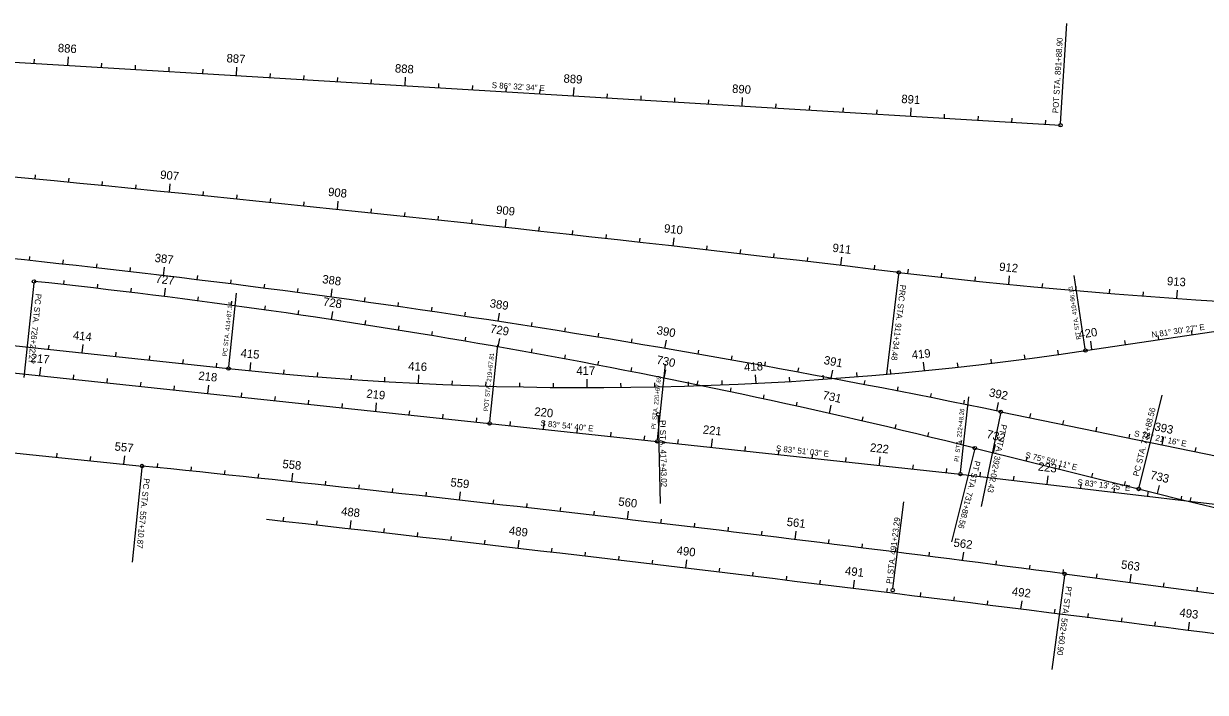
# Model space of a CAD drawing. Extents: x 919452 to 931278, y 583254 to 665650.
# Drawn here: x 927014 to 927714, y 636499 to 636895 of the extents above; entities that cross this region are included whole.
import ezdxf

# ---------------------------------------------------------------- set-up
doc = ezdxf.new("R2010")
doc.units = 0
for name, color, linetype in [('LaneLine', 7, 'Continuous'), ('PMStripe24W', 7, 'Continuous'), ('Scratch1_dp', 7, 'Continuous'), ('ScratchEle_dp', 7, 'Continuous'), ('ShldrHatch', 7, 'Continuous'), ('TollReader', 7, 'Continuous')]:
    doc.layers.add(name, color=color, linetype=linetype)

msp = doc.modelspace()

# ---------------------------------------------------------------- linework, layer by layer
at = {"layer": 'LaneLine'}
for p, q in [((927628.15, 636835.87), (927631.73, 636895.12)), ((927532.16, 636746.7), (927525.07, 636687.36)), ((927642.72, 636702.37), (927636.23, 636745.83)), ((927020.08, 636741.37), (927014.11, 636685.5)), ((927135.47, 636691.73), (927140.13, 636735.38)), ((927290.06, 636659.14), (927294.92, 636704.74)), ((927389.37, 636648.55), (927394.15, 636693.33)), ((927674.6, 636620.31), (927688.23, 636674.91)), ((927568.9, 636629.21), (927573.72, 636673.98)), ((927389.82, 636662.59), (927390.9, 636610.77)), ((927592.52, 636664.14), (927581.17, 636609.04)), ((927577.09, 636642.59), (927563.49, 636588.08)), ((927084.11, 636631.97), (927078.38, 636576.07)), ((927528.88, 636560.37), (927535.2, 636611.74)), ((927630.37, 636568.06), (927623.04, 636512.38))]:
    msp.add_line(p, q, dxfattribs=at)
for centre in [(927628.09, 636834.88), (927532.27, 636747.7), (927020.19, 636742.37), (927642.87, 636701.38), (927135.36, 636690.73), (927389.8, 636663.59), (927592.72, 636665.12), (927289.95, 636658.15), (927389.26, 636647.56), (927577.33, 636643.56), (927084.21, 636632.96), (927568.79, 636628.21), (927674.36, 636619.34), (927630.5, 636569.05), (927528.76, 636559.38)]:
    msp.add_circle(centre, 1, dxfattribs=at)
at = {"layer": 'Scratch1_dp'}
for p, q in [((927020.31, 636871.59), (927020.46, 636874.09)), ((927060.23, 636869.18), (927060.38, 636871.68)), ((927080.2, 636867.98), (927080.35, 636870.47)), ((927100.16, 636866.77), (927100.31, 636869.27)), ((927120.12, 636865.56), (927120.27, 636868.06)), ((927160.05, 636863.15), (927160.2, 636865.65)), ((927180.01, 636861.95), (927180.17, 636864.44)), ((927199.98, 636860.74), (927200.13, 636863.24)), ((927219.94, 636859.53), (927220.09, 636862.03)), ((927259.87, 636857.12), (927260.02, 636859.62)), ((927279.83, 636855.92), (927279.98, 636858.41)), ((927299.8, 636854.71), (927299.95, 636857.2)), ((927319.76, 636853.5), (927319.91, 636856)), ((927359.69, 636851.09), (927359.84, 636853.59)), ((927379.65, 636849.89), (927379.8, 636852.38)), ((927399.61, 636848.68), (927399.76, 636851.17)), ((927419.58, 636847.47), (927419.73, 636849.97)), ((927459.5, 636845.06), (927459.66, 636847.56)), ((927479.47, 636843.85), (927479.62, 636846.35)), ((927499.43, 636842.65), (927499.58, 636845.14)), ((927519.4, 636841.44), (927519.55, 636843.94)), ((927559.32, 636839.03), (927559.47, 636841.53)), ((927579.29, 636837.82), (927579.44, 636840.32)), ((927599.25, 636836.62), (927599.4, 636839.11)), ((927619.21, 636835.41), (927619.36, 636837.91)), ((927020.78, 636802.98), (927021.02, 636805.47)), ((927040.69, 636801.04), (927040.93, 636803.53)), ((927060.59, 636799.09), (927060.84, 636801.58)), ((927080.5, 636797.12), (927080.74, 636799.61)), ((927120.3, 636793.13), (927120.55, 636795.62)), ((927140.2, 636791.11), (927140.45, 636793.6)), ((927160.09, 636789.07), (927160.35, 636791.56)), ((927179.99, 636787.01), (927180.24, 636789.5)), ((927219.77, 636782.85), (927220.03, 636785.34)), ((927239.66, 636780.74), (927239.92, 636783.23)), ((927259.54, 636778.62), (927259.81, 636781.1)), ((927279.43, 636776.47), (927279.7, 636778.96)), ((927319.19, 636772.14), (927319.47, 636774.62)), ((927339.07, 636769.94), (927339.35, 636772.43)), ((927358.95, 636767.73), (927359.23, 636770.21)), ((927378.82, 636765.5), (927379.1, 636767.98)), ((927418.57, 636760.99), (927418.85, 636763.47)), ((927438.44, 636758.71), (927438.72, 636761.19)), ((927458.31, 636756.41), (927458.59, 636758.89)), ((927017.46, 636754.73), (927017.73, 636757.21)), ((927037.35, 636752.58), (927037.62, 636755.07)), ((927057.22, 636750.37), (927057.5, 636752.85)), ((927478.17, 636754.09), (927478.46, 636756.58)), ((927517.9, 636749.41), (927518.19, 636751.89)), ((927077.09, 636748.09), (927077.38, 636750.58)), ((927116.81, 636743.34), (927117.12, 636745.82)), ((927537.76, 636747.05), (927538.05, 636749.53)), ((927557.63, 636744.77), (927557.9, 636747.25)), ((927577.51, 636742.61), (927577.77, 636745.1)), ((927037.82, 636740.45), (927038.09, 636742.93)), ((927057.69, 636738.19), (927057.98, 636740.67)), ((927077.55, 636735.83), (927077.85, 636738.31)), ((927136.66, 636740.86), (927136.97, 636743.34)), ((927156.49, 636738.32), (927156.82, 636740.79)), ((927176.32, 636735.7), (927176.65, 636738.18)), ((927617.31, 636738.67), (927617.55, 636741.16)), ((927637.23, 636736.88), (927637.45, 636739.37)), ((927657.16, 636735.21), (927657.37, 636737.7)), ((927117.23, 636730.83), (927117.56, 636733.31)), ((927137.06, 636728.18), (927137.4, 636730.66)), ((927215.95, 636730.28), (927216.3, 636732.76)), ((927677.1, 636733.66), (927677.29, 636736.16)), ((927156.87, 636725.44), (927157.22, 636727.91)), ((927176.67, 636722.6), (927177.03, 636725.07)), ((927235.76, 636727.48), (927236.11, 636729.95)), ((927255.55, 636724.6), (927255.91, 636727.07)), ((927275.33, 636721.66), (927275.7, 636724.13)), ((927216.22, 636716.63), (927216.6, 636719.1)), ((927314.86, 636715.58), (927315.25, 636718.05)), ((927235.97, 636713.5), (927236.37, 636715.96)), ((927255.71, 636710.27), (927256.12, 636712.74)), ((927275.43, 636706.95), (927275.85, 636709.41)), ((927334.62, 636712.44), (927335.01, 636714.9)), ((927354.36, 636709.23), (927354.76, 636711.7)), ((927686.26, 636707.86), (927685.89, 636710.33)), ((927706.04, 636710.81), (927705.67, 636713.28)), ((927028.83, 636702.1), (927029.09, 636704.58)), ((927314.83, 636700.01), (927315.27, 636702.47)), ((927374.09, 636705.96), (927374.5, 636708.42)), ((927666.48, 636704.9), (927666.11, 636707.38)), ((927068.6, 636697.85), (927068.87, 636700.34)), ((927088.49, 636695.73), (927088.75, 636698.22)), ((927108.37, 636693.61), (927108.64, 636696.1)), ((927334.5, 636696.4), (927334.96, 636698.86)), ((927354.15, 636692.7), (927354.62, 636695.15)), ((927413.52, 636699.21), (927413.95, 636701.68)), ((927433.21, 636695.74), (927433.65, 636698.21)), ((927587.24, 636693.87), (927586.94, 636696.35)), ((927607.09, 636696.37), (927606.76, 636698.84)), ((927626.9, 636699.06), (927626.56, 636701.54)), ((927128.26, 636691.49), (927128.53, 636693.98)), ((927168.06, 636687.52), (927168.29, 636690)), ((927187.99, 636685.82), (927188.19, 636688.31)), ((927373.79, 636688.9), (927374.27, 636691.35)), ((927452.9, 636692.21), (927453.34, 636694.67)), ((927472.57, 636688.61), (927473.02, 636691.06)), ((927507.65, 636685.87), (927507.45, 636688.36)), ((927527.58, 636687.57), (927527.35, 636690.06)), ((927567.38, 636691.57), (927567.1, 636694.06)), ((927043.54, 636684.44), (927043.8, 636686.92)), ((927063.42, 636682.32), (927063.69, 636684.8)), ((927083.31, 636680.19), (927083.58, 636682.68)), ((927207.94, 636684.32), (927208.11, 636686.82)), ((927227.89, 636683.03), (927228.04, 636685.52)), ((927267.84, 636681.04), (927267.94, 636683.53)), ((927287.83, 636680.34), (927287.91, 636682.84)), ((927307.82, 636679.84), (927307.87, 636682.34)), ((927327.82, 636679.55), (927327.85, 636682.05)), ((927367.82, 636679.55), (927367.8, 636682.05)), ((927387.82, 636679.86), (927387.77, 636682.35)), ((927407.81, 636680.36), (927407.74, 636682.86)), ((927413, 636681), (927413.51, 636683.45)), ((927427.8, 636681.06), (927427.7, 636683.56)), ((927467.75, 636683.07), (927467.6, 636685.56)), ((927487.71, 636684.37), (927487.53, 636686.86)), ((927511.88, 636681.2), (927512.35, 636683.66)), ((927103.2, 636678.07), (927103.46, 636680.56)), ((927142.97, 636673.83), (927143.24, 636676.32)), ((927162.86, 636671.71), (927163.12, 636674.19)), ((927432.58, 636676.91), (927433.09, 636679.36)), ((927452.14, 636672.73), (927452.66, 636675.17)), ((927531.52, 636677.4), (927531.99, 636679.86)), ((927551.14, 636673.54), (927551.63, 636675.99)), ((927182.75, 636669.59), (927183.01, 636672.07)), ((927202.63, 636667.47), (927202.9, 636669.95)), ((927471.67, 636668.45), (927472.21, 636670.89)), ((927570.75, 636669.61), (927571.24, 636672.06)), ((927242.41, 636663.22), (927242.67, 636665.71)), ((927262.3, 636661.1), (927262.56, 636663.59)), ((927282.18, 636658.98), (927282.45, 636661.47)), ((927510.68, 636659.6), (927511.25, 636662.04)), ((927609.93, 636661.58), (927610.44, 636664.02)), ((927302.07, 636656.86), (927302.33, 636659.34)), ((927341.84, 636652.61), (927342.11, 636655.1)), ((927530.15, 636655.04), (927530.73, 636657.47)), ((927629.52, 636657.54), (927630.03, 636659.99)), ((927649.11, 636653.5), (927649.61, 636655.95)), ((927361.73, 636650.49), (927362, 636652.98)), ((927381.62, 636648.37), (927381.88, 636650.86)), ((927401.5, 636646.24), (927401.77, 636648.72)), ((927549.6, 636650.38), (927550.19, 636652.81)), ((927569.03, 636645.62), (927569.63, 636648.05)), ((927668.7, 636649.46), (927669.2, 636651.91)), ((927033.61, 636638.15), (927033.86, 636640.64)), ((927441.27, 636641.95), (927441.54, 636644.44)), ((927461.16, 636639.81), (927461.43, 636642.3)), ((927481.04, 636637.67), (927481.31, 636640.15)), ((927707.87, 636641.39), (927708.38, 636643.84)), ((927053.5, 636636.11), (927053.76, 636638.6)), ((927093.3, 636632.03), (927093.55, 636634.52)), ((927113.19, 636629.97), (927113.45, 636632.46)), ((927500.93, 636635.53), (927501.2, 636638.01)), ((927540.7, 636631.24), (927540.97, 636633.73)), ((927607.84, 636635.95), (927608.45, 636638.37)), ((927627.25, 636631.1), (927627.85, 636633.53)), ((927133.08, 636627.89), (927133.34, 636630.38)), ((927152.97, 636625.79), (927153.23, 636628.27)), ((927560.58, 636629.1), (927560.85, 636631.58)), ((927580.45, 636626.83), (927580.75, 636629.31)), ((927600.31, 636624.47), (927600.61, 636626.95)), ((927646.65, 636626.26), (927647.26, 636628.69)), ((927192.74, 636621.52), (927193.01, 636624.01)), ((927212.62, 636619.36), (927212.9, 636621.85)), ((927232.5, 636617.18), (927232.78, 636619.66)), ((927640.04, 636619.75), (927640.33, 636622.23)), ((927659.9, 636617.39), (927660.19, 636619.87)), ((927666.06, 636621.42), (927666.66, 636623.84)), ((927252.38, 636614.97), (927252.66, 636617.46)), ((927292.13, 636610.5), (927292.41, 636612.99)), ((927679.76, 636615.03), (927680.05, 636617.51)), ((927699.62, 636612.67), (927699.91, 636615.15)), ((927704.9, 636611.85), (927705.48, 636614.28)), ((927312, 636608.24), (927312.29, 636610.72)), ((927331.87, 636605.95), (927332.16, 636608.43)), ((927351.74, 636603.64), (927352.03, 636606.13)), ((927167.76, 636600.16), (927168.04, 636602.64)), ((927187.63, 636597.9), (927187.92, 636600.38)), ((927391.46, 636598.97), (927391.76, 636601.45)), ((927411.32, 636596.6), (927411.62, 636599.08)), ((927227.37, 636593.36), (927227.66, 636595.84)), ((927247.24, 636591.07), (927247.53, 636593.55)), ((927267.11, 636588.77), (927267.4, 636591.25)), ((927431.18, 636594.21), (927431.48, 636596.69)), ((927451.03, 636591.8), (927451.34, 636594.28)), ((927286.98, 636586.46), (927287.27, 636588.95)), ((927326.71, 636581.81), (927327, 636584.3)), ((927490.74, 636586.91), (927491.04, 636589.39)), ((927510.58, 636584.44), (927510.89, 636586.92)), ((927530.43, 636581.95), (927530.74, 636584.43)), ((927346.57, 636579.47), (927346.86, 636581.96)), ((927366.43, 636577.12), (927366.72, 636579.6)), ((927386.29, 636574.76), (927386.59, 636577.24)), ((927550.27, 636579.43), (927550.58, 636581.91)), ((927589.94, 636574.34), (927590.26, 636576.82)), ((927426.01, 636570), (927426.3, 636572.49)), ((927445.86, 636567.61), (927446.16, 636570.09)), ((927609.78, 636571.77), (927610.1, 636574.25)), ((927629.61, 636569.17), (927629.93, 636571.65)), ((927465.72, 636565.21), (927466.02, 636567.69)), ((927485.57, 636562.79), (927485.87, 636565.27)), ((927649.44, 636566.56), (927649.76, 636569.04)), ((927689.09, 636561.35), (927689.42, 636563.83)), ((927525.27, 636557.93), (927525.58, 636560.41)), ((927545.12, 636555.48), (927545.43, 636557.96)), ((927564.97, 636553.03), (927565.28, 636555.51)), ((927708.92, 636558.74), (927709.25, 636561.22)), ((927584.82, 636550.56), (927585.13, 636553.04)), ((927624.51, 636545.59), (927624.82, 636548.07)), ((927644.35, 636543.09), (927644.67, 636545.57)), ((927664.2, 636540.58), (927664.51, 636543.06)), ((927684.04, 636538.06), (927684.35, 636540.54))]:
    msp.add_line(p, q, dxfattribs=at)
at = {"layer": 'ScratchEle_dp'}
for p, q in [((926993.81, 636873.2), (927628.09, 636834.88)), ((926652.85, 636742.2), (927135.36, 636690.73)), ((926651.16, 636726.29), (927289.95, 636658.15)), ((927642.87, 636701.38), (927761.55, 636719.1)), ((926620.06, 636680.55), (927084.21, 636632.96)), ((927592.72, 636665.12), (927788.61, 636624.75)), ((927289.95, 636658.15), (927389.26, 636647.56)), ((927389.26, 636647.56), (927568.79, 636628.21)), ((927577.33, 636643.56), (927674.36, 636619.34)), ((927568.79, 636628.21), (927746.27, 636607.13)), ((927630.5, 636569.05), (928164.62, 636498.82))]:
    msp.add_line(p, q, dxfattribs=at)
for centre, radius, start, end in [((924808.61, 613941.45), 22968.31, 83.189634, 85.623449), ((926386.43, 630812.14), 5976, 78.354474, 84.656985), ((927919.83, 639992.88), 3268.24, 263.18963, 272.20538), ((926584.51, 632665.58), 4100, 75.98637, 83.89999), ((927347.51, 638679.45), 2000, 263.91108, 278.49255), ((925121.35, 617487.67), 19245.65, 82.508751, 84.146229), ((928618.75, 640403.27), 3900, 255.98637, 261.64217), ((922956.96, 599413.81), 37423.99, 82.411957, 83.554939)]:
    msp.add_arc(centre, radius, start, end, dxfattribs=at)
at = {"layer": 'TollReader'}
for p, q in [((927040.27, 636870.39), (927040.57, 636875.38)), ((927140.09, 636864.36), (927140.39, 636869.35)), ((927239.91, 636858.33), (927240.21, 636863.32)), ((927339.72, 636852.3), (927340.02, 636857.29)), ((927439.54, 636846.27), (927439.84, 636851.26)), ((927539.36, 636840.24), (927539.66, 636845.23)), ((927100.4, 636795.14), (927100.9, 636800.11)), ((927199.88, 636784.94), (927200.4, 636789.91)), ((927299.31, 636774.31), (927299.85, 636779.28)), ((927398.7, 636763.25), (927399.26, 636768.22)), ((927498.03, 636751.76), (927498.62, 636756.73)), ((927096.96, 636745.75), (927097.55, 636750.71)), ((927597.41, 636740.58), (927597.9, 636745.56)), ((927097.4, 636733.38), (927098.02, 636738.34)), ((927196.14, 636733.03), (927196.82, 636737.98)), ((927697.05, 636732.24), (927697.39, 636737.23)), ((927196.45, 636719.66), (927197.2, 636724.6)), ((927295.1, 636718.65), (927295.86, 636723.59)), ((927048.71, 636699.98), (927049.24, 636704.95)), ((927295.14, 636703.53), (927296, 636708.45)), ((927393.81, 636702.62), (927394.65, 636707.55)), ((927646.69, 636701.95), (927645.96, 636706.9)), ((927023.65, 636686.56), (927024.18, 636691.53)), ((927148.15, 636689.41), (927148.65, 636694.38)), ((927393.4, 636685), (927394.39, 636689.9)), ((927492.23, 636684.94), (927493.16, 636689.85)), ((927547.49, 636689.47), (927546.99, 636694.45)), ((927247.86, 636681.93), (927248.11, 636686.93)), ((927347.82, 636679.45), (927347.82, 636684.45)), ((927447.78, 636681.96), (927447.53, 636686.96)), ((927123.09, 636675.95), (927123.62, 636680.92)), ((927222.52, 636665.34), (927223.05, 636670.32)), ((927491.19, 636664.07), (927492.29, 636668.95)), ((927590.34, 636665.61), (927591.35, 636670.51)), ((927321.96, 636654.74), (927322.49, 636659.71)), ((927421.39, 636644.1), (927421.92, 636649.07)), ((927688.29, 636645.43), (927689.3, 636650.32)), ((927588.44, 636640.79), (927589.65, 636645.64)), ((927073.4, 636634.07), (927073.91, 636639.04)), ((927520.81, 636633.38), (927521.35, 636638.36)), ((927172.86, 636623.67), (927173.39, 636628.64)), ((927620.17, 636622.11), (927620.76, 636627.07)), ((927685.46, 636616.59), (927686.66, 636621.44)), ((927272.26, 636612.75), (927272.82, 636617.72)), ((927371.6, 636601.31), (927372.19, 636606.28)), ((927207.5, 636595.63), (927208.07, 636600.6)), ((927470.89, 636589.36), (927471.5, 636594.33)), ((927306.84, 636584.14), (927307.42, 636589.11)), ((927406.15, 636572.39), (927406.74, 636577.35)), ((927570.11, 636576.9), (927570.74, 636581.86)), ((927505.42, 636560.37), (927506.03, 636565.33)), ((927669.26, 636563.96), (927669.92, 636568.91)), ((927604.67, 636548.08), (927605.29, 636553.04)), ((927703.87, 636535.53), (927704.51, 636540.49))]:
    msp.add_line(p, q, dxfattribs=at)

# ---------------------------------------------------------------- texts
at = {"layer": 'LaneLine'}
for s, height, rotation, p in [('POT STA. 891+88.90', 3.5, 86.54273, (927626.77, 636841.97)), ('PRC STA. 911+34.48', 3.5, 263.18963, (927533.18, 636740.54)), ('PT STA. 419+96.13', 2.625, 98.49255, (927640.1, 636708.04)), ('PC STA. 726+22.27', 3.5, 263.89999, (927021.19, 636735.22)), ('PC STA. 414+87.14', 2.625, 83.91108, (927134.36, 636697.88)), ('POT STA. 219+67.81', 2.625, 83.91108, (927288.96, 636665.3)), ('PI  STA. 220+67.69', 2.625, 83.91108, (927388.26, 636654.7)), ('PC STA. 732+88.56', 3.5, 75.98637, (927674.35, 636626.56)), ('PI  STA. 222+48.26', 2.625, 83.8509, (927567.8, 636635.36)), ('PI STA. 417+43.02', 3.5, 271.20181, (927390.74, 636660.11)), ('PT STA. 392+02.43', 3.5, 258.35447, (927593.02, 636657.91)), ('PT STA. 731+88.56', 3.5, 255.98637, (927577.34, 636636.34)), ('PC STA. 557+10.87', 3.5, 264.14623, (927085.24, 636625.82)), ('PI STA. 491+23.29', 3.5, 82.98345, (927528.32, 636562.96)), ('PT STA. 562+60.90', 3.5, 262.50875, (927631.32, 636561.89))]:
    msp.add_text(s, height=height, rotation=rotation, dxfattribs=at).set_placement(p)
at = {"layer": 'PMStripe24W'}
for s, rotation, p in [('S 86%%d 32\' 34" E', 356.54273, (927291.17, 636856.98)), ('N 81%%d 30\' 27" E', 8.49255, (927682.28, 636709.03)), ('S 83%%d 54\' 40" E', 353.91108, (927319.98, 636656.71)), ('S 78%%d 21\' 16" E', 348.35447, (927671.5, 636650.67)), ('S 83%%d 51\' 03" E', 353.8509, (927459.41, 636641.76)), ('S 75%%d 59\' 11" E', 345.98637, (927606.94, 636637.97)), ('S 83%%d 13\' 25" E', 353.22367, (927637.95, 636621.76))]:
    msp.add_text(s, height=3.5, rotation=rotation, dxfattribs=at).set_placement(p)
at = {"layer": 'ShldrHatch'}
for s, rotation, p in [('886', 356.54273, (927034.2, 636878.27)), ('887', 356.54273, (927134.08, 636872.23)), ('888', 356.54273, (927233.8, 636866.21)), ('889', 356.54273, (927333.65, 636860.18)), ('890', 356.54273, (927433.48, 636854.15)), ('891', 356.54273, (927533.69, 636848.09)), ('907', 354.27347, (927094.71, 636803.24)), ('908', 354.02401, (927194.12, 636793.08)), ('909', 353.77456, (927293.63, 636782.48)), ('910', 353.5251, (927393.06, 636771.44)), ('387', 353.17159, (927091.42, 636753.96)), ('911', 353.27565, (927492.82, 636759.93)), ('912', 354.33827, (927591.59, 636748.69)), ('727', 352.81375, (927091.91, 636741.63)), ('388', 352.21282, (927190.65, 636741.35)), ('913', 356.09138, (927690.99, 636740.17)), ('728', 351.41629, (927191.07, 636728.06)), ('389', 351.25406, (927289.79, 636727.06)), ('729', 350.01883, (927290, 636712.05)), ('414', 353.91108, (927043.06, 636708.12)), ('390', 350.29529, (927388.64, 636711.11)), ('420', 8.49255, (927639.14, 636708.4)), ('415', 354.27948, (927142.37, 636697.53)), ('419', 5.73863, (927540.24, 636696.28)), ('217', 353.91108, (927018.01, 636694.7)), ('730', 348.62138, (927388.49, 636693.64)), ('391', 349.33653, (927487.59, 636693.44)), ('218', 353.91108, (927117.35, 636684.11)), ('416', 357.14426, (927241.71, 636689.75)), ('417', 0.00905, (927341.35, 636686.95)), ('418', 2.87384, (927440.84, 636689.13)), ('219', 353.91108, (927216.82, 636673.49)), ('731', 347.22392, (927486.86, 636672.75)), ('392', 348.37776, (927585.41, 636674.29)), ('220', 353.91108, (927316.27, 636662.89)), ('221', 353.8509, (927416.09, 636652.21)), ('732', 345.98637, (927583.86, 636649.66)), ('393', 348.35447, (927683.35, 636654.1)), ('557', 354.14623, (927067.73, 636642.19)), ('222', 353.8509, (927515.07, 636641.55)), ('558', 353.88088, (927167.12, 636631.82)), ('223', 353.22367, (927614.52, 636630.33)), ('559', 353.58318, (927266.6, 636620.93)), ('733', 346.15448, (927680.86, 636625.45)), ('560', 353.28547, (927366, 636609.53)), ('488', 353.47839, (927201.83, 636603.83)), ('561', 352.98776, (927465.71, 636597.56)), ('489', 353.32529, (927301.22, 636592.35)), ('490', 353.17219, (927400.56, 636580.61)), ('562', 352.69005, (927564.53, 636585.18)), ('563', 352.50875, (927663.71, 636572.25)), ('491', 353.01909, (927500.24, 636568.56)), ('492', 352.86599, (927599.06, 636556.34)), ('493', 352.71289, (927698.29, 636543.8))]:
    msp.add_text(s, height=5, rotation=rotation, dxfattribs=at).set_placement(p)

doc.saveas('drawing.dxf')
